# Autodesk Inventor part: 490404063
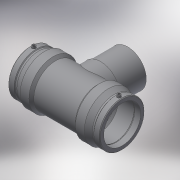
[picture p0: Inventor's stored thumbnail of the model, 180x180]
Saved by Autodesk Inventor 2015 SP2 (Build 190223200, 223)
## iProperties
Created: 2017-06
Part Number: 490404063
Material: Generic
Description: PLASSON TEE 63-63-63
Document SubType Name: Modeling
Designer: KIM
Mass: 409.396 g
Surface Area: 1080.91 cm^2
Volume: 409.396 cm^3
Density: 1 g/cm^3
Appearance: Default
Author: KIM
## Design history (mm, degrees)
derived "490404.ipt"
feature "Solid1::490404.ipt"
tag "TaggingFeature1"
body "Solid1"
other parameters: "d0" = 167, "d1" = 63, "d2" = 82, "d3" = 58, "d4" = 41.75, "d5" = 73.8, "d6" = 59.85, "d7" = 63, "d8" = 168 deg, "d10" = 23.2, "d11" = 7.73333, "d13" = 167, "d14" = 17.6296, "d17" = 56.7, "d18" = 63, "d19" = 3.52592, "d20" = 168 deg, "d22" = 76.26, "d23" = 82, "d24" = 73.9722, "d25" = 135 deg, "d26" = 116.9, "d27" = 135 deg, "d29" = 58, "d30" = 15, "d31" = 66.8, "d34" = 5 deg, "d35" = 15, "d39" = 5 deg, "d40" = 9.6, "d41" = 4.8, "d42" = 6, "d43" = 0, "d45" = 4, "d46" = 14, "d47" = 0, "d48" = -119, "d49" = 63, "d51" = 0, "d52" = 50.4, "d54" = 0, "d55" = 73.8, "d56" = 82, "d57" = 58.45, "d58" = 135 deg, "d59" = 58, "d60" = 58, "d61" = 135 deg, "d62" = 119, "d72" = 75.985, "d73" = 37.9925, "d74" = -119, "d75" = 66.15, "d77" = 0, "d78" = 50.4, "d80" = 0, "d81" = 63, "d82" = 78, "d83" = 0, "d84" = 3, "d85" = 0, "d86" = 3, "d87" = 0, "d88" = 16.82, "d89" = 4.205, "d90" = 16.82, "d_" = 63, "L_" = 167, "L_1" = 58, "D_" = 82, "A_" = 58, "d_2" = 12, "H_" = 119
